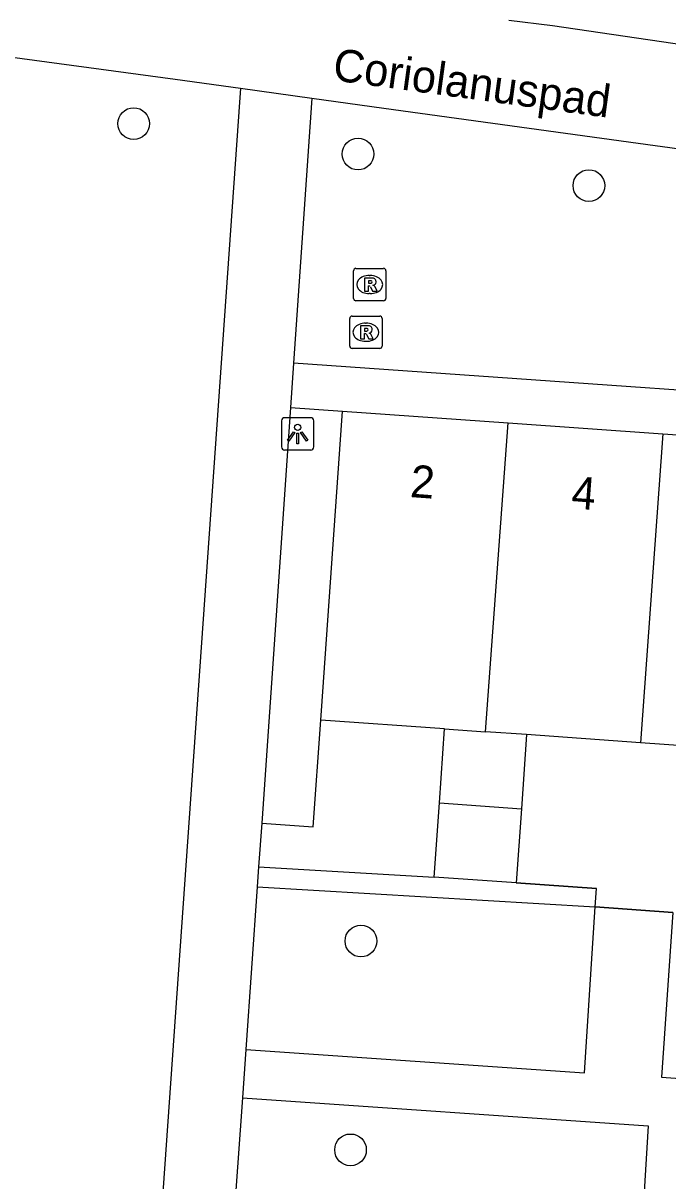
# Model space of a CAD drawing. Extents: x 161848 to 162726, y 385382 to 386521.
# Drawn here: x 162118.77 to 162138.7, y 386056.94 to 386092.69 of the extents above; entities that cross this region are included whole.
import ezdxf

# ---------------------------------------------------------------- set-up
doc = ezdxf.new("R2010")
doc.units = 0
for name, color, linetype in [('IMGEO_Boom', 7, 'Continuous'), ('IMGEO_Groenvoorziening', 7, 'Continuous'), ('IMGEO_Hek', 7, 'Continuous'), ('IMGEO_Lichtpunt', 7, 'Continuous'), ('IMGEO_Openbare_ruimte_label', 7, 'Continuous'), ('IMGEO_Pand', 7, 'Continuous'), ('IMGEO_Pand_nummerreeks', 7, 'Continuous'), ('IMGEO_Rioolput', 7, 'Continuous'), ('IMGEO_Voetpad_halfverhard', 7, 'Continuous'), ('IMGEO_Voetpad_open', 7, 'Continuous')]:
    doc.layers.add(name, color=color, linetype=linetype)

msp = doc.modelspace()

# ---------------------------------------------------------------- linework, layer by layer
at = {"layer": 'IMGEO_Boom'}
for centre in [(162122.185, 386089.584), (162129.121, 386088.641), (162136.256, 386087.67), (162129.21, 386064.34), (162128.889, 386057.895)]:
    msp.add_circle(centre, 0.489, dxfattribs=at)
at = {"layer": 'IMGEO_Groenvoorziening'}
for points in [[(162126.144, 386067.978), (162127.739, 386067.865), (162127.971, 386071.162)], [(162126.047, 386066.633), (162131.475, 386066.319)], [(162136.455, 386065.401), (162136.492, 386065.967), (162134.009, 386066.141)], [(162126.006, 386066.02), (162136.455, 386065.401)]]:
    msp.add_lwpolyline(points, dxfattribs=at)
at = {"layer": 'IMGEO_Hek'}
for points in [[(162126.144, 386067.978), (162127.739, 386067.865), (162127.971, 386071.162)], [(162126.144, 386067.978), (162126.047, 386066.633), (162131.475, 386066.319)], [(162134.009, 386066.141), (162136.492, 386065.967)], [(162138.85, 386065.226), (162136.455, 386065.401), (162136.492, 386065.967)]]:
    msp.add_lwpolyline(points, dxfattribs=at)
at = {"layer": 'IMGEO_Lichtpunt'}
for p, q in [((162126.757, 386080.406), (162126.757, 386079.599)), ((162126.757, 386080.406), (162126.757, 386079.599)), ((162127.659, 386080.501), (162126.851, 386080.501)), ((162127.659, 386080.501), (162126.851, 386080.501)), ((162127.753, 386079.599), (162127.753, 386080.406)), ((162127.753, 386079.599), (162127.753, 386080.406)), ((162126.851, 386079.505), (162127.659, 386079.505)), ((162126.851, 386079.505), (162127.659, 386079.505))]:
    msp.add_line(p, q, dxfattribs=at)
for points in [[(162127.131, 386080.07), (162127.17, 386080.042), (162126.982, 386079.78), (162126.944, 386079.807), (162127.131, 386080.07)], [(162127.233, 386080.022), (162127.28, 386080.022), (162127.28, 386079.7), (162127.233, 386079.7), (162127.233, 386080.022)], [(162127.343, 386080.042), (162127.381, 386080.069), (162127.568, 386079.807), (162127.529, 386079.779), (162127.343, 386080.042)]]:
    msp.add_lwpolyline(points, dxfattribs=at)
msp.add_circle((162127.256, 386080.204), 0.0994, dxfattribs=at)
for centre, start, end in [((162126.851, 386080.406), 90, 180), ((162126.851, 386080.406), 90, 180), ((162127.659, 386080.406), 0, 90), ((162127.659, 386080.406), 0, 90), ((162126.851, 386079.599), 180, 270), ((162126.851, 386079.599), 180, 270), ((162127.659, 386079.599), 270, 0), ((162127.659, 386079.599), 270, 360)]:
    msp.add_arc(centre, 0.0946, start, end, dxfattribs=at)
at = {"layer": 'IMGEO_Pand'}
for points in [[(162127.971, 386071.162), (162128.643, 386080.705)], [(162128.643, 386080.705), (162133.76, 386080.345)], [(162133.064, 386070.804), (162133.76, 386080.345)], [(162133.76, 386080.345), (162138.547, 386080.008)], [(162138.547, 386080.008), (162137.851, 386070.467)], [(162138.547, 386080.008), (162143.336, 386079.671)], [(162131.797, 386070.893), (162127.971, 386071.162)], [(162131.636, 386068.607), (162131.797, 386070.893)], [(162131.797, 386070.893), (162133.064, 386070.804)], [(162134.331, 386070.715), (162133.064, 386070.804)], [(162134.331, 386070.715), (162134.17, 386068.428)], [(162137.851, 386070.467), (162134.331, 386070.715)], [(162141.371, 386070.219), (162137.851, 386070.467)], [(162131.475, 386066.319), (162131.636, 386068.607)], [(162131.636, 386068.607), (162134.17, 386068.428)], [(162134.17, 386068.428), (162134.009, 386066.141)], [(162134.009, 386066.141), (162131.475, 386066.319)]]:
    msp.add_lwpolyline(points, dxfattribs=at)
at = {"layer": 'IMGEO_Rioolput'}
for p, q in [((162128.983, 386084.188), (162128.983, 386085.04)), ((162129.058, 386085.114), (162129.91, 386085.114)), ((162129.984, 386085.04), (162129.984, 386084.188)), ((162129.471, 386084.894), (162129.496, 386084.894)), ((162129.494, 386084.334), (162129.469, 386084.334)), ((162129.91, 386084.114), (162129.058, 386084.114)), ((162128.864, 386082.714), (162128.864, 386083.566)), ((162128.939, 386083.64), (162129.791, 386083.64)), ((162129.865, 386083.566), (162129.865, 386082.714)), ((162129.352, 386083.42), (162129.377, 386083.42)), ((162129.375, 386082.86), (162129.35, 386082.86)), ((162129.791, 386082.64), (162128.939, 386082.64))]:
    msp.add_line(p, q, dxfattribs=at)
for points in [[(162128.983, 386084.188), (162128.983, 386085.04)], [(162129.058, 386085.114), (162129.91, 386085.114)], [(162129.984, 386085.04), (162129.984, 386084.188)], [(162129.572, 386084.812), (162129.32, 386084.814), (162129.32, 386084.414)], [(162129.498, 386084.733), (162129.444, 386084.733), (162129.444, 386084.652)], [(162129.444, 386084.652), (162129.496, 386084.652)], [(162129.32, 386084.414), (162129.444, 386084.414), (162129.444, 386084.576), (162129.455, 386084.576)], [(162129.502, 386084.547), (162129.573, 386084.414), (162129.713, 386084.414), (162129.648, 386084.54)], [(162129.91, 386084.114), (162129.058, 386084.114)], [(162128.864, 386082.714), (162128.864, 386083.566)], [(162128.939, 386083.64), (162129.791, 386083.64)], [(162129.865, 386083.566), (162129.865, 386082.714)], [(162129.453, 386083.338), (162129.201, 386083.34), (162129.201, 386082.94)], [(162129.379, 386083.259), (162129.325, 386083.259), (162129.325, 386083.178)], [(162129.201, 386082.94), (162129.325, 386082.94), (162129.325, 386083.102), (162129.336, 386083.102)], [(162129.325, 386083.178), (162129.377, 386083.178)], [(162129.383, 386083.073), (162129.454, 386082.94), (162129.594, 386082.94), (162129.529, 386083.066)], [(162129.791, 386082.64), (162128.939, 386082.64)]]:
    msp.add_lwpolyline(points, dxfattribs=at)
for centre, radius, start, end in [((162129.06, 386085.038), 0.0765, 91.552, 178.448), ((162129.06, 386085.038), 0.0765, 91.552, 178.448), ((162129.908, 386085.038), 0.0765, 1.552, 88.448), ((162129.908, 386085.038), 0.0765, 1.552, 88.448), ((162129.48, 386084.841), 0.19, 274.7715, 282.9687), ((162129.504, 386084.637), 0.0964, 77.0061, 93.1865), ((162129.518, 386084.694), 0.0378, 276.6634, 79.6772), ((162129.571, 386084.702), 0.109, 350.3612, 89.416), ((162129.569, 386084.702), 0.112, 277.5842, 350.9817), ((162129.454, 386084.523), 0.0533, 26.0293, 88.6989), ((162129.553, 386084.487), 0.108, 29.5134, 73.7905), ((162129.06, 386084.19), 0.0765, 181.552, 268.448), ((162129.06, 386084.19), 0.0765, 181.552, 268.448), ((162129.908, 386084.19), 0.0765, 271.552, 358.448), ((162129.908, 386084.19), 0.0765, 271.552, 358.448), ((162128.941, 386083.564), 0.0765, 91.552, 178.448), ((162128.941, 386083.564), 0.0765, 91.552, 178.448), ((162129.789, 386083.564), 0.0765, 1.552, 88.448), ((162129.789, 386083.564), 0.0765, 1.552, 88.448), ((162129.361, 386083.367), 0.19, 274.7715, 282.9687), ((162129.385, 386083.163), 0.0964, 77.0061, 93.1865), ((162129.399, 386083.22), 0.0378, 276.6634, 79.6772), ((162129.452, 386083.228), 0.109, 350.3612, 89.416), ((162129.45, 386083.228), 0.112, 277.5842, 350.9817), ((162129.335, 386083.049), 0.0533, 26.0293, 88.6989), ((162129.434, 386083.013), 0.108, 29.5134, 73.7905), ((162128.941, 386082.716), 0.0765, 181.552, 268.448), ((162128.941, 386082.716), 0.0765, 181.552, 268.448), ((162129.789, 386082.716), 0.0765, 271.552, 358.448), ((162129.789, 386082.716), 0.0765, 271.552, 358.448)]:
    msp.add_arc(centre, radius, start, end, dxfattribs=at)
for centre, major_axis, ratio, start_param, end_param in [((162129.47, 386084.614), (-0.387, 0.002), 0.722429, 4.712389, 7.853982), ((162129.495, 386084.614), (-0.39, 0.002), 0.717154, 1.570796, 4.712389), ((162129.351, 386083.14), (-0.387, 0.002), 0.722429, 4.712389, 7.853982), ((162129.376, 386083.14), (-0.39, 0.002), 0.717154, 1.570796, 4.712389)]:
    msp.add_ellipse(centre, major_axis=major_axis, ratio=ratio, start_param=start_param, end_param=end_param, dxfattribs=at)
at = {"layer": 'IMGEO_Voetpad_halfverhard'}
for points in [[(162125.652, 386060.996), (162136.12, 386060.273), (162136.455, 386065.401)], [(162136.455, 386065.401), (162138.85, 386065.226)], [(162138.85, 386065.226), (162138.499, 386060.134), (162148.032, 386059.461), (162148.371, 386064.587)], [(162125.547, 386059.505), (162138.09, 386058.64), (162137.906, 386055.577)]]:
    msp.add_lwpolyline(points, dxfattribs=at)
at = {"layer": 'IMGEO_Voetpad_open'}
for points in [[(162093.503, 386094.936), (162098.826, 386094.292), (162123.469, 386090.954), (162125.487, 386090.674)], [(162155.201, 386089.654), (162135.134, 386092.605), (162133.786, 386092.767)], [(162125.487, 386090.674), (162122.884, 386053.657), (162122.5, 386048.906), (162122.074, 386042.731)], [(162125.487, 386090.674), (162127.695, 386090.368)], [(162127.695, 386090.368), (162127.128, 386082.182)], [(162127.695, 386090.368), (162129.924, 386090.059), (162137.776, 386088.983), (162139.063, 386088.806), (162149.907, 386087.271)], [(162127.128, 386082.182), (162127.034, 386080.818)], [(162149.453, 386080.622), (162127.128, 386082.182)], [(162127.034, 386080.818), (162126.144, 386067.978)], [(162127.034, 386080.818), (162128.643, 386080.705)], [(162126.144, 386067.978), (162126.047, 386066.633)], [(162126.047, 386066.633), (162126.006, 386066.02)], [(162126.006, 386066.02), (162125.652, 386060.996)], [(162125.652, 386060.996), (162125.547, 386059.505)], [(162125.547, 386059.505), (162125.325, 386056.363), (162125.278, 386055.714)]]:
    msp.add_lwpolyline(points, dxfattribs=at)

# ---------------------------------------------------------------- texts
at = {"layer": 'IMGEO_Openbare_ruimte_label'}
msp.add_text('Coriolanuspad', height=1, rotation=352.2426, dxfattribs=at).set_placement((162128.308, 386090.928))
at = {"layer": 'IMGEO_Pand_nummerreeks'}
for s, p in [('2', (162130.713, 386078.054)), ('4', (162135.693, 386077.704))]:
    msp.add_text(s, height=1, rotation=355.7773, dxfattribs=at).set_placement(p)

doc.saveas('drawing.dxf')
